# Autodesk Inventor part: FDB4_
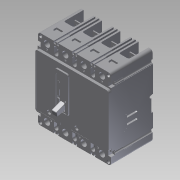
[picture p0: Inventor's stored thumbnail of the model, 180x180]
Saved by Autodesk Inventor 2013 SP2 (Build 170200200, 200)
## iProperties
Created: 2014-08
Part Number: FDB4_
Material: Generic
Document SubType Name: Modeling
Designer: DM/JS
Density: 1 g/cm^3
Description: TYPE FDB THERMAL MAGNETIC CIRCUIT BREAKERS FOUR POLE, SERIES C
Translation Standard: STEP AP214IS
FileName: Y:\ECO-062745\WIP\New\FD4_.stp
PreProcessor: Autodesk Inventor 2012
PostProcessor: Build: 219, Release: 2012 SP2 - Date: Fri 04/27/2012
Sent Units: inch
Uncertainty: 0.00039370078740199997
MXEDIT: false
MXINVTNRV: INV Versioned Component|FDB4_|003.0
Author: DM/JS
Revision Number: 003
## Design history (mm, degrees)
node "FDB4_"
node "L1"
node "L2"
node "L3"
node "L4"
node "T1"
node "T2"
node "T3"
node "T4"
body "Solid1"
node "Base1"
